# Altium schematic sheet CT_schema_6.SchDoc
size 454 x 431 mm
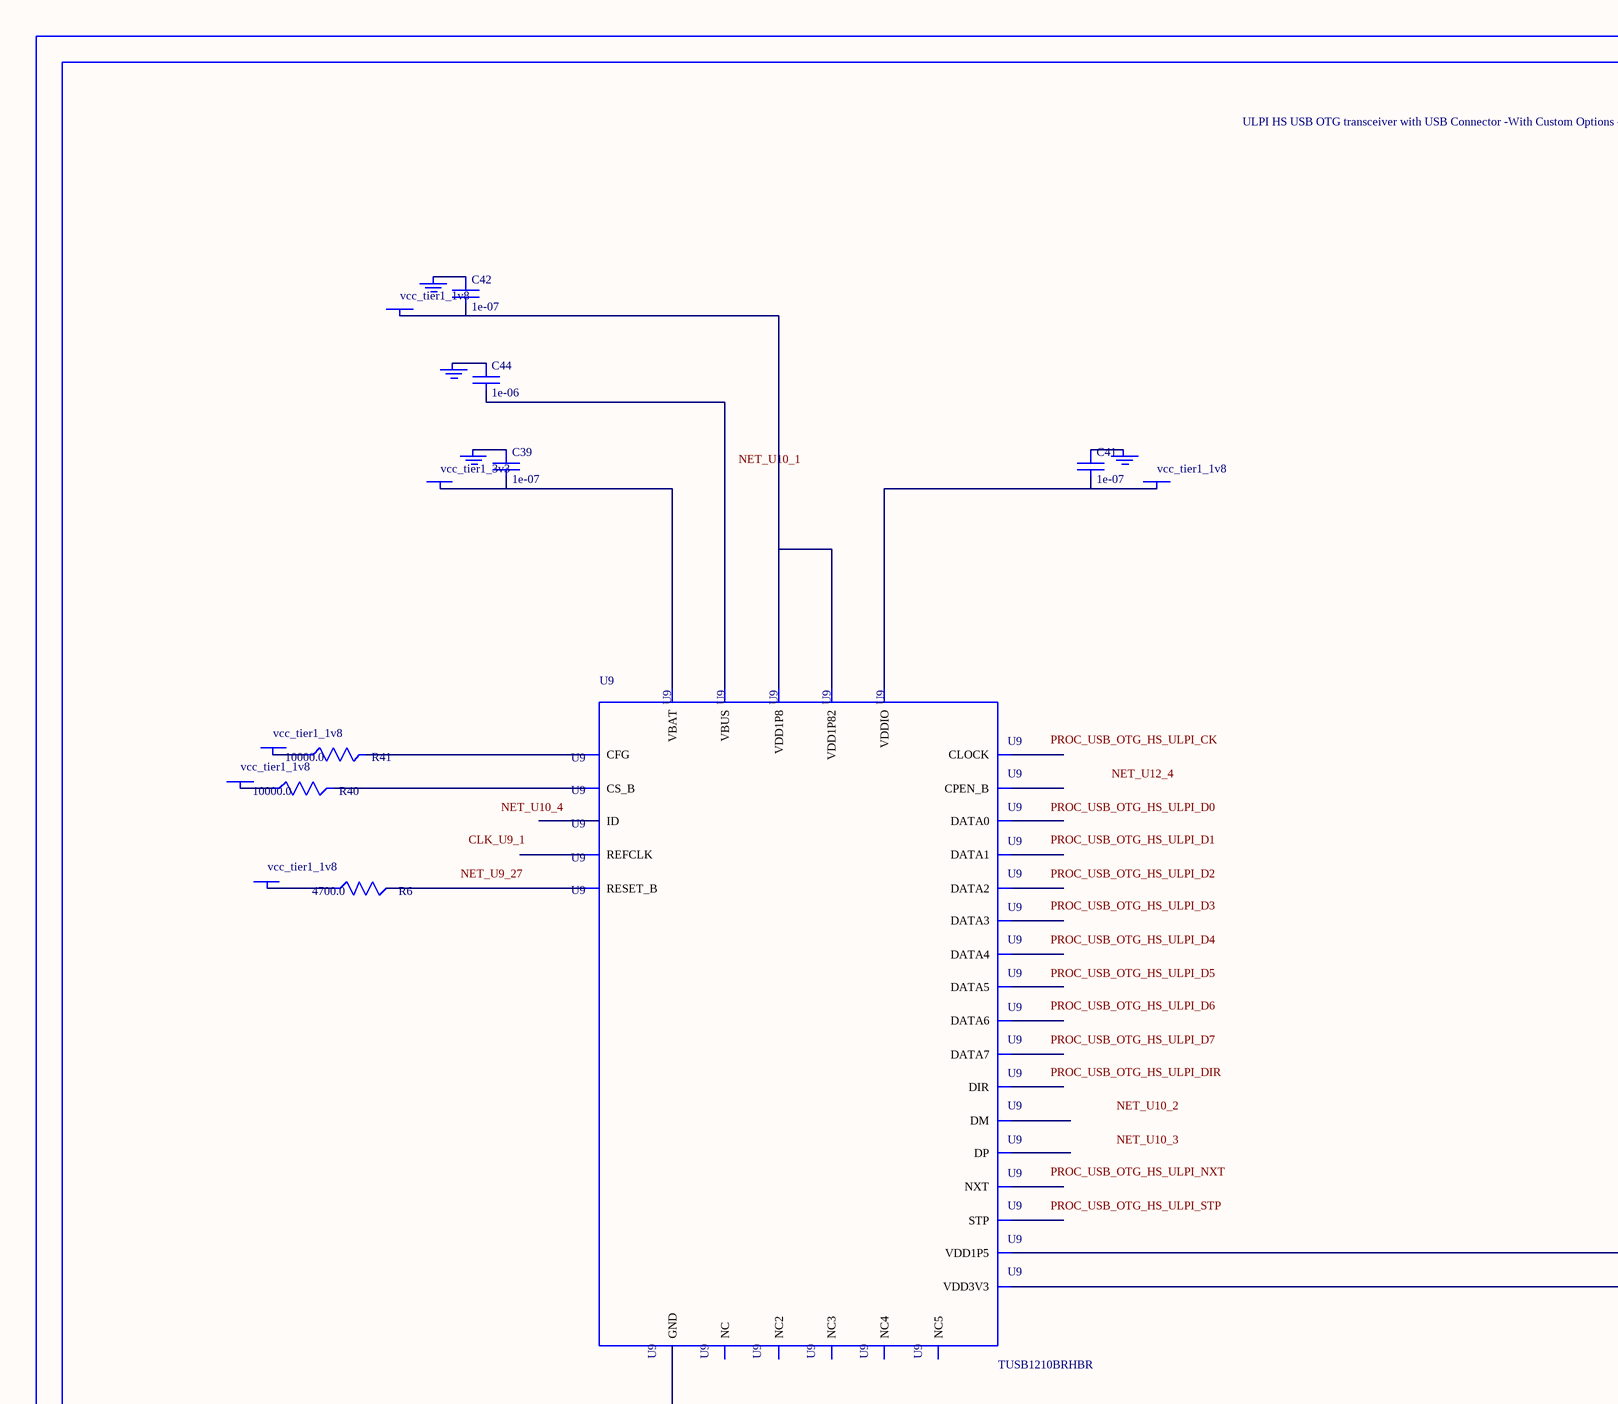
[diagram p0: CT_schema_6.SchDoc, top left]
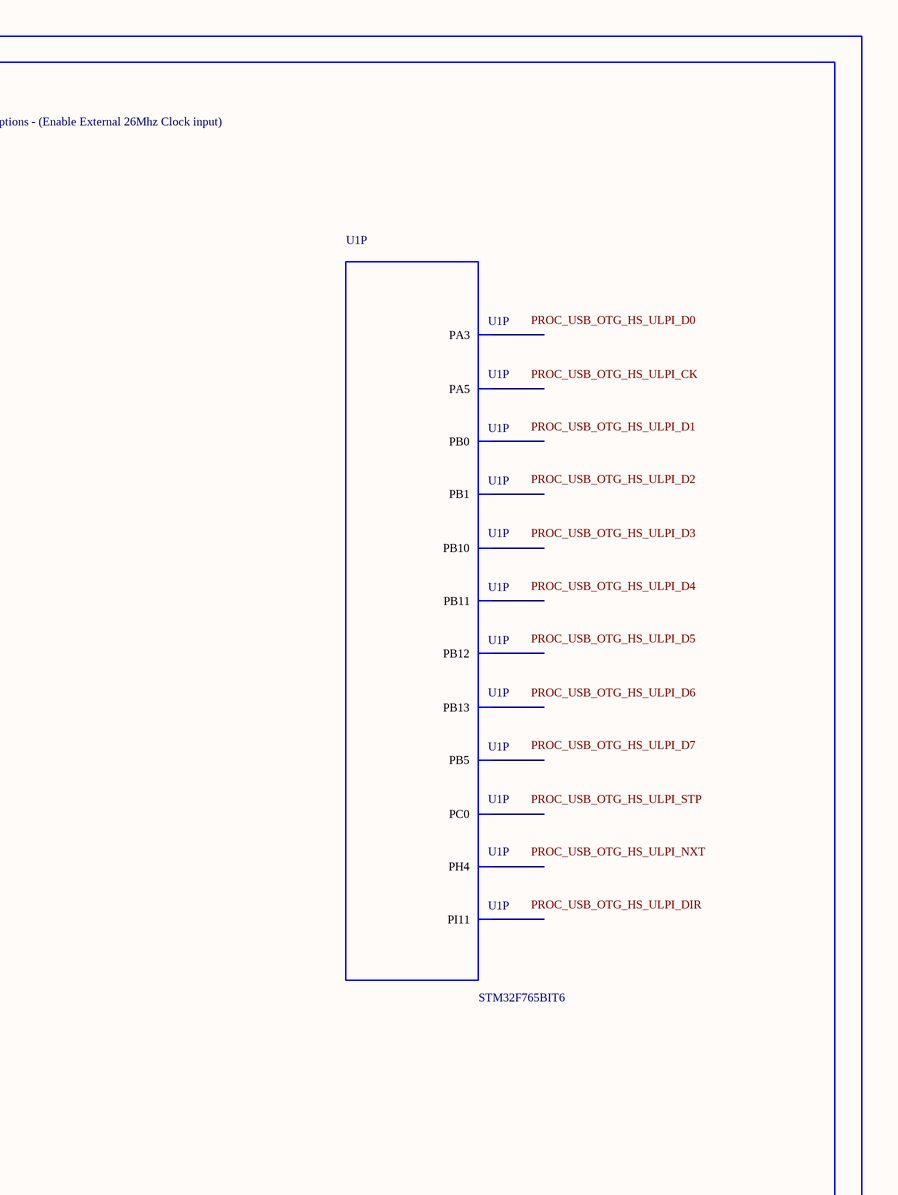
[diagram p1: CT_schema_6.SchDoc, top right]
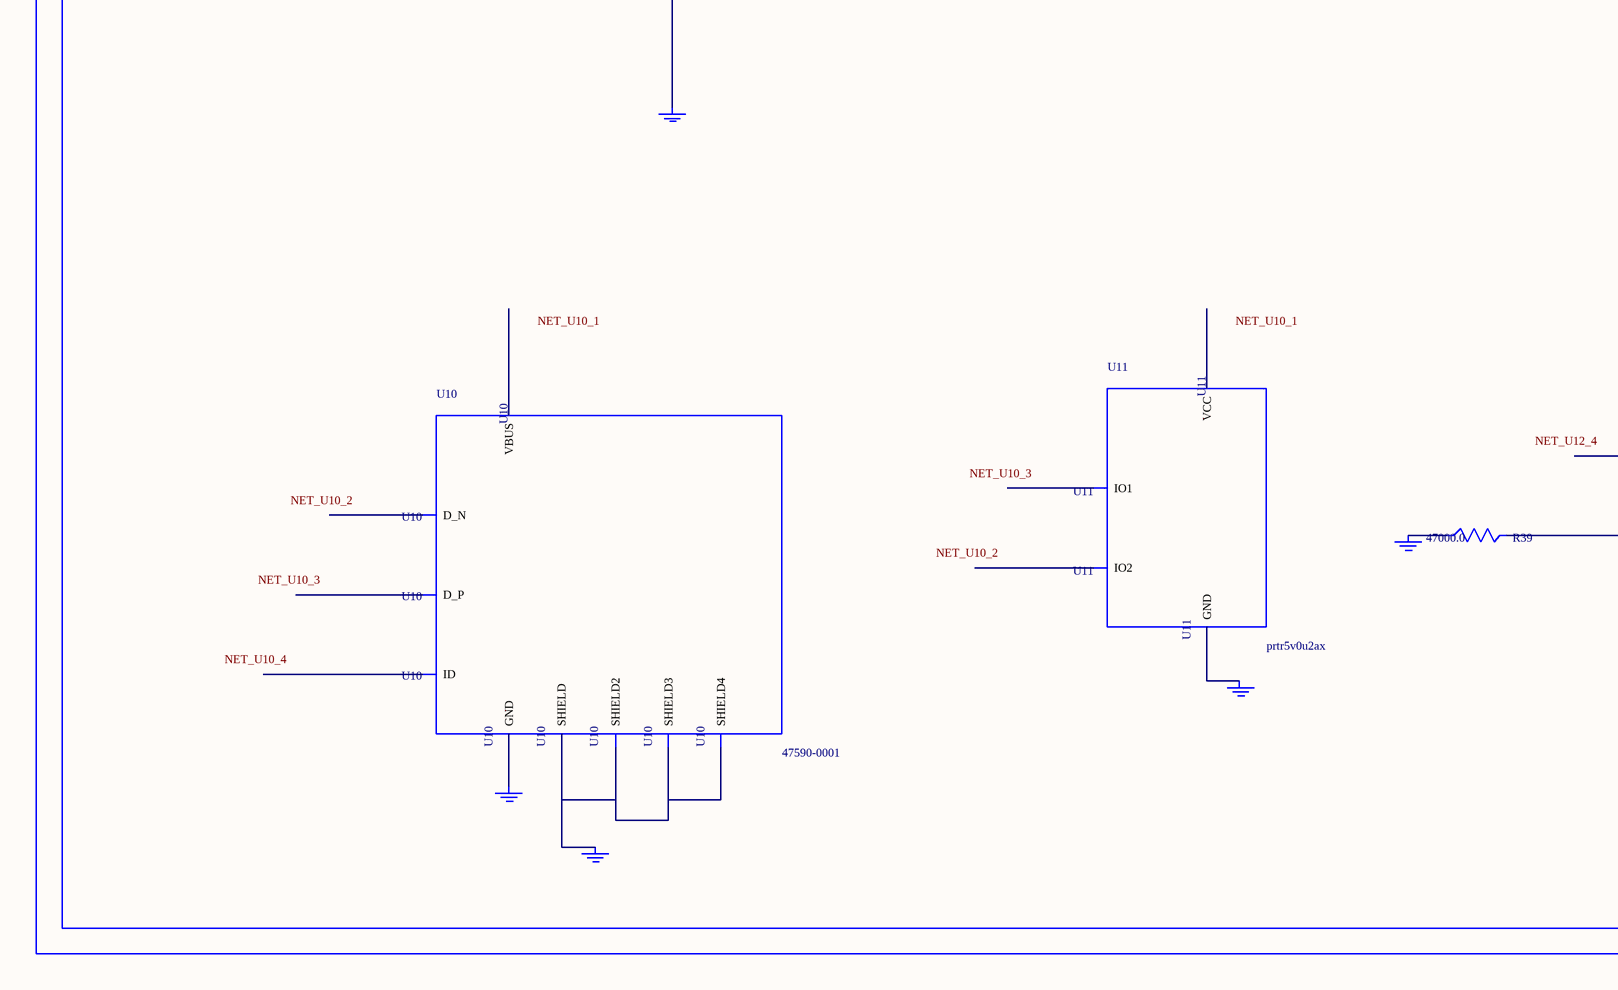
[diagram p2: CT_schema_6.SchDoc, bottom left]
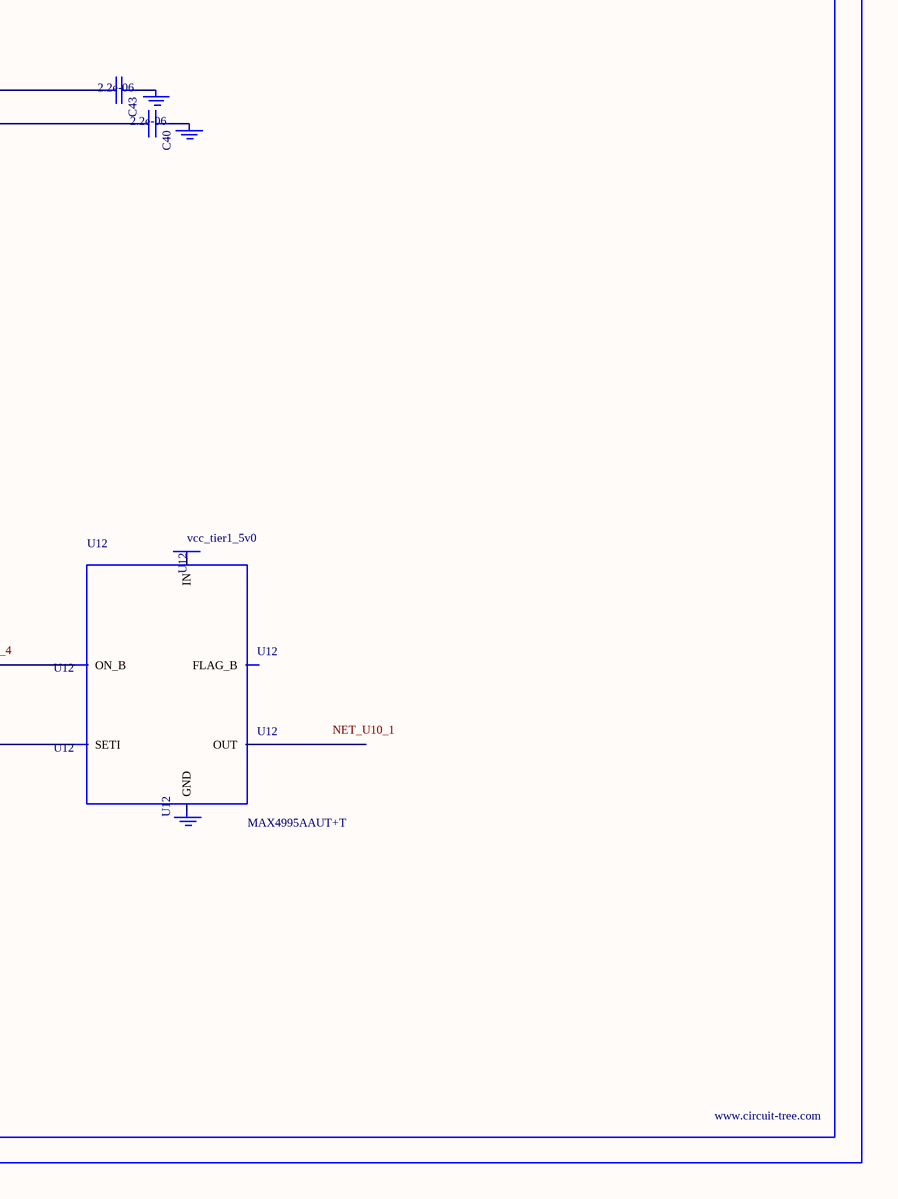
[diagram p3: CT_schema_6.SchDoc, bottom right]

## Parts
BORDER5  (no value)
C39  1e-07  [C0402]
C40  2.2e-06  [C0603]
C41  1e-07  [C0402]
C42  1e-07  [C0402]
C43  2.2e-06  [C0603]
C44  1e-06  [C0603]
GND_INSTANCE_5_0  (no value)
GND_INSTANCE_5_1  (no value)
GND_INSTANCE_5_2  (no value)
GND_INSTANCE_5_3  (no value)
GND_INSTANCE_5_4  (no value)
GND_INSTANCE_5_5  (no value)
GND_INSTANCE_5_6  (no value)
GND_INSTANCE_5_7  (no value)
GND_INSTANCE_5_8  (no value)
GND_INSTANCE_5_9  (no value)
GND_INSTANCE_5_10  (no value)
GND_INSTANCE_5_11  (no value)
POWER_INSTANCE_5_0  vcc_tier1_1v8
POWER_INSTANCE_5_1  vcc_tier1_1v8
POWER_INSTANCE_5_2  vcc_tier1_3v3
POWER_INSTANCE_5_3  vcc_tier1_1v8
POWER_INSTANCE_5_4  vcc_tier1_1v8
POWER_INSTANCE_5_5  vcc_tier1_1v8
POWER_INSTANCE_5_6  vcc_tier1_5v0
R6  4700.0  [R0603]
R39  47000.0  [R0603]
R40  10000.0  [R0603]
R41  10000.0  [R0603]
U1  STM32F765BIT6  [LQFP208]  (part P of 17)
U9  TUSB1210BRHBR  [RHB32_3P45X3P45]
U10  47590-0001  [MICRO_USB_AB]
U11  prtr5v0u2ax  [SOT143B]
U12  MAX4995AAUT+T  [SOT-23-6]

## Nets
NetC39_1: C39.1 GND_INSTANCE_5_2.0(GND)
NetC39_2: C39.2 POWER_INSTANCE_5_2.0(PWR) U9.21(VBAT)
NetC40_1: C40.1 GND_INSTANCE_5_1.0(GND)
NetC40_2: C40.2 U9.20(VDD3V3)
NetC41_1: C41.1 GND_INSTANCE_5_5.0(GND)
NetC41_2: C41.2 POWER_INSTANCE_5_4.0(PWR) U9.32(VDDIO)
NetC42_1: C42.1 GND_INSTANCE_5_4.0(GND)
NetC42_2: C42.2 POWER_INSTANCE_5_3.0(PWR) U9.28(VDD1P8) U9.30(VDD1P82)
NetC43_1: C43.1 GND_INSTANCE_5_0.0(GND)
NetC43_2: C43.2 U9.12(VDD1P5)
NetC44_1: C44.1 GND_INSTANCE_5_3.0(GND)
NetC44_2: C44.2 U9.22(VBUS)
NetGND_INSTANCE_5_6_0: GND_INSTANCE_5_6.0(GND) U9.33(GND)
NetGND_INSTANCE_5_7_0: GND_INSTANCE_5_7.0(GND) U10.6(SHIELD) U10.7(SHIELD2) U10.8(SHIELD3) U10.9(SHIELD4)
NetGND_INSTANCE_5_8_0: GND_INSTANCE_5_8.0(GND) U10.5(GND)
NetGND_INSTANCE_5_9_0: GND_INSTANCE_5_9.0(GND) U11.1(GND)
NetGND_INSTANCE_5_10_0: GND_INSTANCE_5_10.0(GND) R39.1
NetPOWER_INSTANCE_5_0_0: POWER_INSTANCE_5_0.0(PWR) R40.1
NetPOWER_INSTANCE_5_1_0: POWER_INSTANCE_5_1.0(PWR) R41.1
NetPOWER_INSTANCE_5_5_0: POWER_INSTANCE_5_5.0(PWR) R6.1
NetR6_2: R6.2 U9.27(RESET_B)
NetR39_2: R39.2 U12.3(SETI)
NetR40_2: R40.2 U9.11(CS_B)
NetR41_2: R41.2 U9.14(CFG)

Not connected (* = marked no-connect by the designer): GND_INSTANCE_5_11 0(GND); POWER_INSTANCE_5_6 0(PWR); U1 13(PI11) 35(PC0) 48(PH4) 50(PA3) 54(PA5) 61(PB0) 62(PB1) 90(PB10) 91(PB11) 104(PB12) 105(PB13) 194(PB5); U9 1(REFCLK) 2(NXT) 3(DATA0) 4(DATA1) 5(DATA2) 6(DATA3) 7(DATA4) 8(NC) 9(DATA5) 10(DATA6) 13(DATA7) 15(NC2) 16(NC3) 17(CPEN_B) 18(DP) 19(DM) 23(ID) 24(NC4) 25(NC5) 26(CLOCK) 29(STP) 31(DIR); U10 1(VBUS) 2(D_N) 3(D_P) 4(ID); U11 2(IO1) 3(IO2) 4(VCC); U12 1(OUT) 2(GND) 4(ON_B) 5(IN) 6(FLAG_B)

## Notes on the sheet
- Labels drawn without touching a wire or pin: CLK_U9_1, NET_U9_27, NET_U10_1, NET_U10_2, NET_U10_3, NET_U10_4, NET_U12_4, PROC_USB_OTG_HS_ULPI_CK, PROC_USB_OTG_HS_ULPI_D0, PROC_USB_OTG_HS_ULPI_D1, PROC_USB_OTG_HS_ULPI_D2, PROC_USB_OTG_HS_ULPI_D3, PROC_USB_OTG_HS_ULPI_D4, PROC_USB_OTG_HS_ULPI_D5, PROC_USB_OTG_HS_ULPI_D6, PROC_USB_OTG_HS_ULPI_D7, PROC_USB_OTG_HS_ULPI_DIR, PROC_USB_OTG_HS_ULPI_NXT, PROC_USB_OTG_HS_ULPI_STP

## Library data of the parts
BORDER5 = BORDER_PAGE5
C39 C41 C42 = C0402C104K3RACTU
C40 C43 = C0603C225K8RACTU
C44 = C0603C105K3RACTU
GND_INSTANCE_5_0-GND_INSTANCE_5_11 = GND
POWER_INSTANCE_5_0-POWER_INSTANCE_5_6 = PWR
R6 = RC0603JR-074K7L
R39 = RC0603JR-0747KL
R40 R41 = RC0603JR-0710KL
